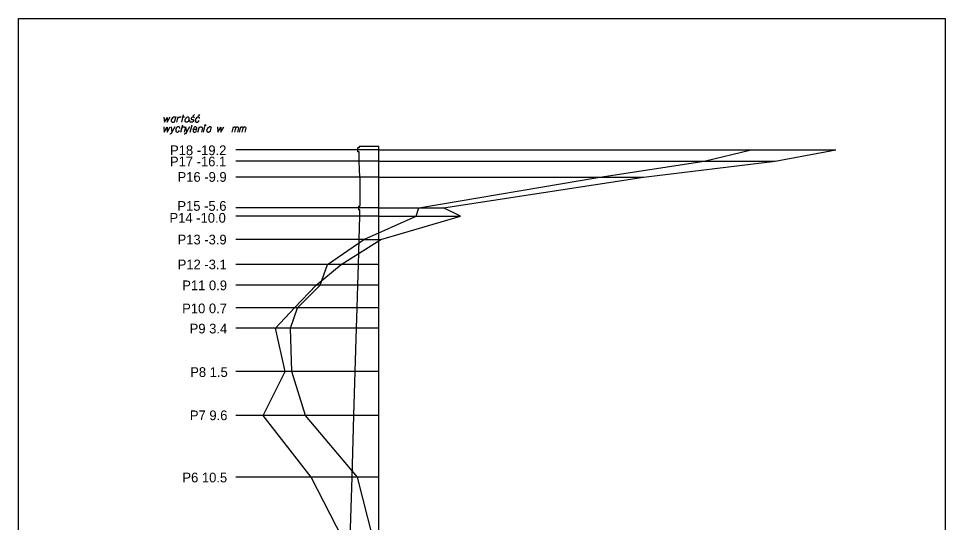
# Model space of a CAD drawing. Extents: x 138 to 6653, y -177 to 1520.
# Drawn here: x 377.01 to 398.01, y -45.34 to -33.92 of the extents above; entities that cross this region are included whole.
import ezdxf

# ---------------------------------------------------------------- set-up
doc = ezdxf.new("R2010")
doc.units = 0
for name, color, linetype in [('15 listopad 2008', 7, 'Continuous'), ('Ramka do drukowania', 7, 'Continuous'), ('Standart wykresów', 7, 'Continuous'), ('Wykresy 4 maj 2008', 7, 'Continuous')]:
    doc.layers.add(name, color=color, linetype=linetype)

msp = doc.modelspace()

# ---------------------------------------------------------------- linework, layer by layer
at = {"layer": '15 listopad 2008'}
msp.add_lwpolyline([(385.168, -52.61), (385.638, -51.164), (385.798, -49.788), (385.628, -48.421), (385.468, -47.063), (385.038, -45.704), (384.688, -44.313), (383.508, -42.911), (383.198, -41.918), (383.168, -40.937), (383.328, -40.478), (383.838, -39.961), (384.008, -39.493), (384.828, -38.925), (386.018, -38.4), (386.078, -38.212), (390.178, -37.514), (392.538, -37.151), (393.608, -36.895)], dxfattribs=at)
at = {"layer": 'Ramka do drukowania'}
for p, q in [((377.007, -33.921), (398.007, -33.921)), ((377.007, -63.621), (377.007, -33.921)), ((398.007, -63.621), (398.007, -33.921))]:
    msp.add_line(p, q, dxfattribs=at)
at = {"layer": 'Standart wykresów'}
for p, q in [((385.168, -36.895), (381.931, -36.895)), ((384.685, -36.853), (384.685, -36.895)), ((384.722, -36.853), (384.685, -36.853)), ((384.685, -36.895), (384.685, -36.937)), ((384.722, -36.937), (384.685, -36.937)), ((384.722, -36.811), (384.722, -36.853)), ((384.722, -36.811), (385.168, -36.811)), ((384.722, -37.151), (384.722, -36.937)), ((385.168, -56.895), (385.168, -36.811)), ((385.168, -37.151), (381.931, -37.151)), ((384.737, -37.514), (384.722, -37.151)), ((385.168, -37.514), (381.931, -37.514)), ((384.737, -37.514), (384.737, -38.168)), ((385.168, -38.212), (381.931, -38.212)), ((384.707, -38.168), (384.707, -38.212)), ((384.707, -38.168), (384.737, -38.168)), ((384.707, -38.212), (384.707, -38.256)), ((385.168, -38.4), (381.931, -38.4)), ((384.741, -38.256), (384.707, -38.256)), ((384.722, -38.925), (384.737, -38.4)), ((384.737, -38.4), (384.741, -38.256)), ((384.828, -38.925), (381.931, -38.925)), ((384.707, -39.493), (384.722, -38.925)), ((384.828, -38.925), (385.216, -38.925)), ((384.008, -39.493), (381.931, -39.493)), ((384.692, -39.961), (384.707, -39.493)), ((383.748, -39.961), (381.931, -39.961)), ((384.68, -40.478), (384.692, -39.961)), ((383.26, -40.478), (381.931, -40.478)), ((384.662, -40.937), (384.68, -40.478)), ((382.827, -40.937), (381.931, -40.937)), ((384.635, -41.918), (384.662, -40.937)), ((383.05, -41.918), (381.931, -41.918)), ((384.605, -42.911), (384.635, -41.918)), ((382.553, -42.911), (381.931, -42.911)), ((384.565, -44.313), (384.605, -42.911)), ((383.639, -44.313), (381.931, -44.313)), ((384.521, -45.704), (384.565, -44.313))]:
    msp.add_line(p, q, dxfattribs=at)
for points in [[(380.704, -36.271), (380.747, -36.105)], [(380.992, -36.093), (380.959, -36.13)], [(381.108, -36.095), (381.075, -36.131)], [(380.301, -36.152), (380.311, -36.271), (380.374, -36.163), (380.375, -36.271), (380.445, -36.15)], [(380.565, -36.161), (380.556, -36.155), (380.534, -36.155), (380.521, -36.157), (380.497, -36.171), (380.477, -36.194), (380.468, -36.219), (380.467, -36.232), (380.468, -36.242), (380.472, -36.252), (380.48, -36.262), (380.489, -36.269), (380.504, -36.271), (380.514, -36.27), (380.525, -36.269), (380.539, -36.261)], [(380.568, -36.151), (380.536, -36.271)], [(380.59, -36.271), (380.623, -36.147)], [(380.615, -36.177), (380.621, -36.172), (380.636, -36.161), (380.652, -36.155), (380.663, -36.151), (380.682, -36.147)], [(380.683, -36.494), (380.726, -36.328)], [(380.704, -36.151), (380.767, -36.151)], [(380.836, -36.151), (380.845, -36.151), (380.856, -36.156), (380.866, -36.171), (380.867, -36.177), (380.869, -36.184), (380.869, -36.189), (380.869, -36.208), (380.865, -36.222), (380.858, -36.237), (380.85, -36.25), (380.837, -36.262), (380.825, -36.271), (380.806, -36.271), (380.798, -36.269), (380.79, -36.262), (380.786, -36.256), (380.781, -36.24), (380.781, -36.216), (380.784, -36.208), (380.789, -36.191), (380.794, -36.182), (380.797, -36.177), (380.81, -36.163), (380.823, -36.155), (380.836, -36.151)], [(380.992, -36.171), (380.988, -36.161), (380.979, -36.155), (380.971, -36.152), (380.959, -36.151), (380.948, -36.152), (380.933, -36.16), (380.922, -36.171), (380.918, -36.18), (380.917, -36.19), (380.92, -36.197), (380.925, -36.201), (380.928, -36.202), (380.935, -36.205), (380.945, -36.206), (380.958, -36.208), (380.966, -36.211), (380.972, -36.219), (380.975, -36.228), (380.973, -36.24), (380.968, -36.25), (380.958, -36.262), (380.948, -36.267), (380.938, -36.27), (380.925, -36.271), (380.909, -36.27), (380.899, -36.265), (380.894, -36.258), (380.891, -36.249), (380.891, -36.24), (380.895, -36.232)], [(380.895, -36.494), (380.938, -36.328)], [(381.107, -36.186), (381.105, -36.171), (381.099, -36.16), (381.091, -36.155), (381.075, -36.152), (381.061, -36.152), (381.043, -36.164), (381.028, -36.184), (381.018, -36.203), (381.014, -36.218), (381.014, -36.24), (381.015, -36.248), (381.02, -36.258), (381.032, -36.269), (381.045, -36.271), (381.06, -36.27), (381.068, -36.267), (381.085, -36.256), (381.098, -36.233)], [(381.233, -36.328), (381.239, -36.328), (381.243, -36.33), (381.247, -36.335), (381.247, -36.342), (381.243, -36.347), (381.239, -36.35), (381.233, -36.35), (381.229, -36.347), (381.225, -36.342), (381.225, -36.335), (381.229, -36.33), (381.233, -36.328)], [(380.3, -36.375), (380.31, -36.494), (380.373, -36.385), (380.374, -36.494), (380.444, -36.372)], [(380.55, -36.372), (380.483, -36.494), (380.462, -36.529), (380.457, -36.532), (380.45, -36.534), (380.437, -36.537), (380.432, -36.537)], [(380.466, -36.373), (380.483, -36.494)], [(380.661, -36.409), (380.659, -36.393), (380.653, -36.383), (380.645, -36.377), (380.629, -36.375), (380.615, -36.375), (380.597, -36.386), (380.582, -36.406), (380.572, -36.426), (380.568, -36.44), (380.568, -36.462), (380.569, -36.47), (380.574, -36.481), (380.586, -36.491), (380.599, -36.494), (380.614, -36.492), (380.622, -36.49), (380.639, -36.478), (380.652, -36.456)], [(380.708, -36.398), (380.712, -36.393), (380.717, -36.385), (380.721, -36.381), (380.724, -36.379), (380.728, -36.376), (380.731, -36.375), (380.735, -36.373), (380.739, -36.372), (380.748, -36.372), (380.755, -36.373), (380.763, -36.376), (380.768, -36.379), (380.772, -36.383), (380.776, -36.388), (380.779, -36.392), (380.78, -36.394), (380.782, -36.4), (380.782, -36.403), (380.758, -36.494)], [(380.877, -36.372), (380.81, -36.494), (380.789, -36.529), (380.784, -36.532), (380.777, -36.534), (380.764, -36.537), (380.759, -36.537)], [(380.793, -36.373), (380.81, -36.494)], [(380.964, -36.424), (381.048, -36.424), (381.049, -36.411), (381.047, -36.4), (381.042, -36.388), (381.026, -36.376), (381.013, -36.375), (381.002, -36.377), (380.988, -36.385), (380.979, -36.394), (380.971, -36.409), (380.966, -36.419), (380.96, -36.441), (380.96, -36.456), (380.962, -36.468), (380.966, -36.478), (380.981, -36.492), (380.992, -36.494), (381.002, -36.492), (381.004, -36.492), (381.021, -36.485), (381.03, -36.475), (381.034, -36.469), (381.035, -36.468), (381.042, -36.456)], [(381.072, -36.494), (381.104, -36.373)], [(381.097, -36.402), (381.1, -36.396), (381.106, -36.388), (381.11, -36.384), (381.115, -36.379), (381.12, -36.376), (381.127, -36.373), (381.133, -36.372), (381.138, -36.372), (381.145, -36.373), (381.15, -36.376), (381.155, -36.379), (381.161, -36.383), (381.166, -36.388), (381.168, -36.392), (381.171, -36.397), (381.174, -36.403), (381.15, -36.494)], [(381.196, -36.494), (381.23, -36.367)], [(381.367, -36.384), (381.358, -36.377), (381.336, -36.377), (381.323, -36.38), (381.299, -36.393), (381.28, -36.417), (381.271, -36.441), (381.269, -36.455), (381.271, -36.465), (381.274, -36.474), (381.282, -36.485), (381.291, -36.491), (381.306, -36.494), (381.316, -36.492), (381.327, -36.491), (381.341, -36.483)], [(381.37, -36.373), (381.339, -36.494)], [(381.515, -36.375), (381.526, -36.494), (381.588, -36.385), (381.59, -36.494), (381.659, -36.372)], [(381.848, -36.494), (381.878, -36.375)], [(381.87, -36.406), (381.876, -36.392), (381.883, -36.384), (381.891, -36.379), (381.899, -36.375), (381.904, -36.372), (381.912, -36.372), (381.914, -36.373), (381.919, -36.379), (381.925, -36.385), (381.929, -36.397), (381.93, -36.403), (381.936, -36.392), (381.944, -36.384), (381.952, -36.379), (381.96, -36.375), (381.967, -36.372), (381.973, -36.372), (381.978, -36.373), (381.982, -36.379), (381.986, -36.385), (381.99, -36.397), (381.991, -36.403), (381.969, -36.494)], [(381.908, -36.494), (381.93, -36.403)], [(382.014, -36.494), (382.044, -36.375)], [(382.036, -36.406), (382.042, -36.392), (382.049, -36.384), (382.057, -36.379), (382.065, -36.375), (382.07, -36.372), (382.078, -36.372), (382.08, -36.373), (382.086, -36.379), (382.091, -36.385), (382.095, -36.397), (382.096, -36.403), (382.103, -36.392), (382.111, -36.384), (382.118, -36.379), (382.126, -36.375), (382.133, -36.372), (382.139, -36.372), (382.145, -36.373), (382.148, -36.379), (382.152, -36.385), (382.156, -36.397), (382.158, -36.403), (382.135, -36.494)], [(382.074, -36.494), (382.096, -36.403)]]:
    msp.add_lwpolyline(points, dxfattribs=at)
at = {"layer": 'Wykresy 4 maj 2008'}
for p, q in [((385.168, -36.895), (395.525, -36.895)), ((385.168, -37.151), (394.148, -37.151)), ((385.168, -37.514), (391.166, -37.514)), ((385.168, -38.212), (386.638, -38.212)), ((385.168, -38.4), (387.017, -38.4)), ((385.168, -39.493), (384.008, -39.493)), ((385.168, -39.961), (383.748, -39.961)), ((385.168, -40.478), (383.26, -40.478)), ((385.168, -40.937), (382.827, -40.937)), ((385.168, -41.918), (383.05, -41.918)), ((385.168, -42.911), (382.553, -42.911)), ((385.168, -44.313), (383.639, -44.313))]:
    msp.add_line(p, q, dxfattribs=at)
msp.add_lwpolyline([(385.168, -52.61), (385.149, -51.164), (385.122, -49.788), (385.16, -48.421), (384.802, -47.063), (384.355, -45.704), (383.639, -44.313), (382.553, -42.911), (383.05, -41.918), (382.827, -40.937), (383.26, -40.478), (383.748, -39.961), (384.313, -39.493), (385.216, -38.925), (387.017, -38.4), (386.638, -38.212), (391.166, -37.514), (394.148, -37.151), (395.525, -36.895)], dxfattribs=at)

# ---------------------------------------------------------------- texts
for s, p in [('P18 -19.2', (380.44, -37.015)), ('P17 -16.1', (380.437, -37.27)), ('P16 -9.9', (380.61, -37.619)), ('P15 -5.6', (380.606, -38.276)), ('P14 -10.0', (380.428, -38.546)), ('P13 -3.9', (380.61, -39.038)), ('P12 -3.1', (380.612, -39.602)), ('P11 0.9', (380.716, -40.075)), ('P10 0.7', (380.715, -40.597)), ('P9 3.4', (380.884, -41.054)), ('P8 1.5', (380.897, -42.04)), ('P7 9.6', (380.889, -43.019)), ('P6 10.5', (380.72, -44.428))]:
    msp.add_text(s, height=0.22, dxfattribs=at).set_placement(p)

doc.saveas('drawing.dxf')
